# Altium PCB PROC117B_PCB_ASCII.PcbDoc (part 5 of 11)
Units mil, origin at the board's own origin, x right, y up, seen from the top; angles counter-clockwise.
Board outline 2480.32 x 3185.25 mil, 8 copper layers (Top Layer, L2_GND1, L3_SIG1, L4_PWR1, L5_PWR2, L6_SIG2, L7_GND2, Bottom Layer), stack 57.4 mil thick; 456 components, 292 nets, 7831 pads, 2905 vias.
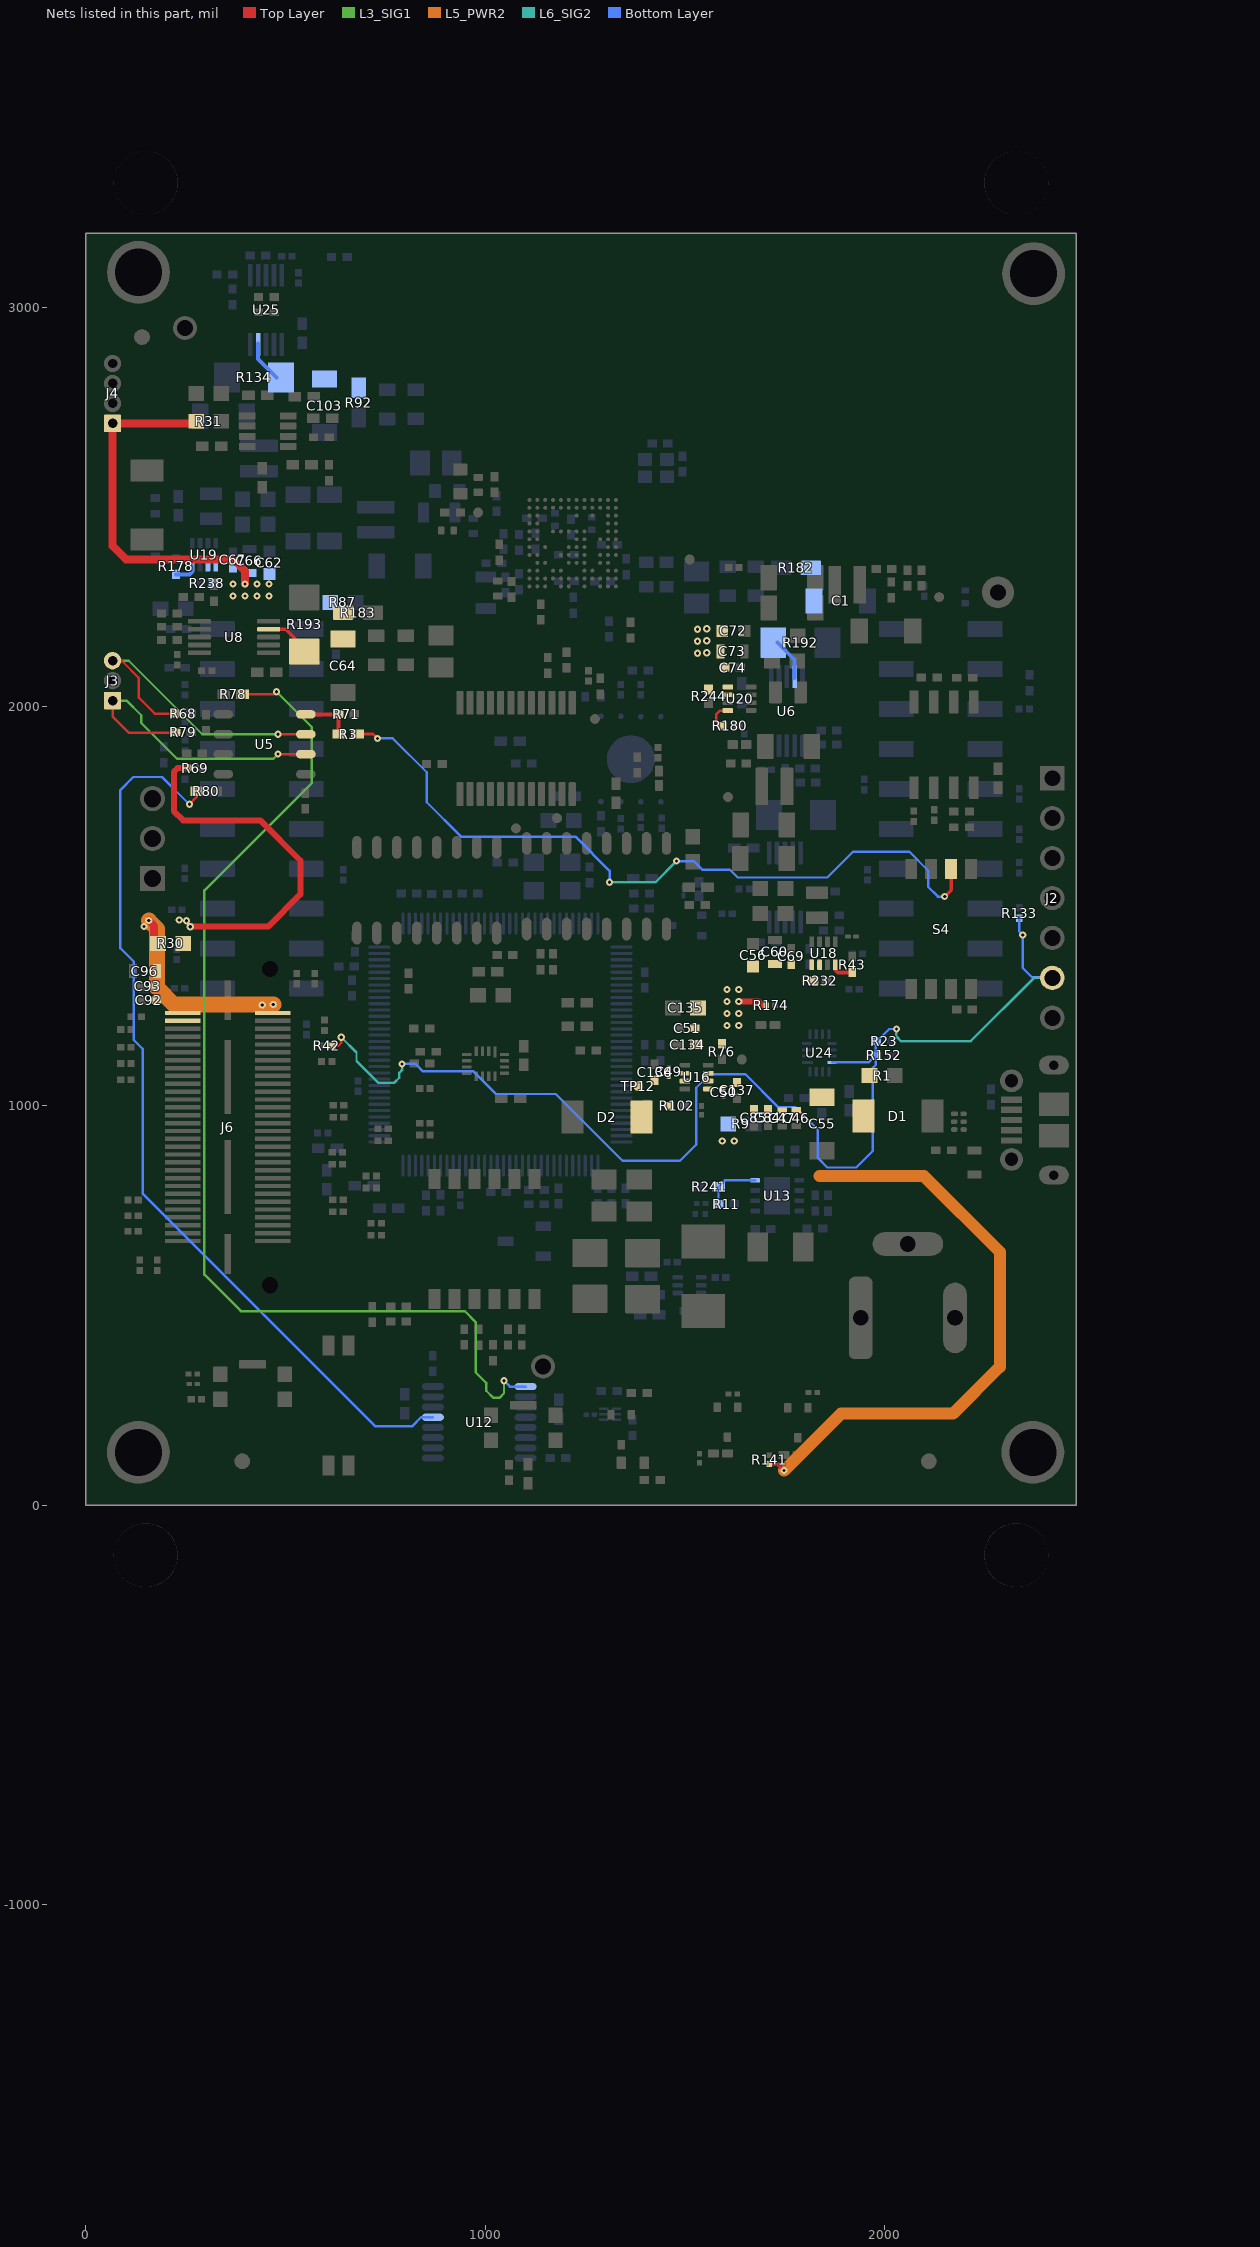
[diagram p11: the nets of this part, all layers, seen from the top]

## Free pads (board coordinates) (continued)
  round 5 on Mech26: 1(807.05,1390.43) 1(807.05,1390.43) 1(807.05,1441.43) 1(807.05,1441.43) 1(818.3,1366.43) 1(818.3,1366.43) 1(818.3,1374.58) 1(818.3,1374.58) 1(818.3,1376.86) 1(818.3,1376.86) 1(818.3,1384.36) 1(818.3,1384.36) 1(818.3,1390.43) 1(818.3,1390.43) 1(827.33,1093.94) 1(827.33,1093.94) 1(827.33,1093.96) 1(827.33,1093.96) 1(827.33,1150.96) 1(827.33,1150.96) 1(827.33,1150.98) 1(827.33,1150.98) 1(830.33,1090.96) 1(830.33,1090.96) 1(830.33,1153.96) 1(830.33,1153.96) 1(835.8,1366.43) 1(835.8,1366.43) 1(835.8,1374.58) 1(835.8,1374.58) 1(835.8,1376.86) 1(835.8,1376.86) 1(835.8,1384.36) 1(835.8,1384.36) 1(835.8,1390.43) 1(835.8,1390.43) 1(839.95,1066.46) 1(839.95,1066.46) 1(839.95,1075.01) 1(839.95,1075.01) 1(839.95,1078.65) 1(839.95,1078.65) 1(839.95,1079.91) 1(839.95,1079.91) 1(839.95,1089.87) 1(839.95,1089.87) 1(839.95,1090.96) 1(839.95,1090.96) 1(839.95,1153.96) 1(839.95,1153.96) 1(839.95,1155.04) 1(839.95,1155.04) 1(839.95,1165.01) 1(839.95,1165.01) 1(839.95,1166.27) 1(839.95,1166.27) 1(839.95,1169.91) 1(839.95,1169.91) 1(839.95,1178.46) 1(839.95,1178.46) 1(854.71,1066.46) 1(854.71,1066.46) 1(854.71,1075.01) 1(854.71,1075.01) 1(854.71,1078.65) 1(854.71,1078.65) 1(854.71,1079.91) 1(854.71,1079.91) 1(854.71,1089.87) 1(854.71,1089.87) 1(854.71,1090.96) 1(854.71,1090.96) 1(854.71,1153.96) 1(854.71,1153.96) 1(854.71,1155.04) 1(854.71,1155.04) 1(854.71,1165.01) 1(854.71,1165.01) 1(854.71,1166.27) 1(854.71,1166.27) 1(854.71,1169.91) 1(854.71,1169.91) 1(854.71,1178.46) 1(854.71,1178.46) 1(855.8,1441.43) 1(855.8,1441.43) 1(855.8,1447.49) 1(855.8,1447.49) 1(855.8,1454.99) 1(855.8,1454.99) 1(855.8,1457.27) 1(855.8,1457.27) 1(855.8,1465.43) 1(855.8,1465.43) 1(873.3,1441.43) 1(873.3,1441.43) 1(873.3,1447.49) 1(873.3,1447.49) 1(873.3,1454.99) 1(873.3,1454.99) 1(873.3,1457.27) 1(873.3,1457.27) 1(873.3,1465.43) 1(873.3,1465.43) 1(877.45,1066.46) 1(877.45,1066.46) 1(877.45,1075.01) 1(877.45,1075.01) 1(877.45,1078.65) 1(877.45,1078.65) 1(877.45,1079.91) 1(877.45,1079.91) 1(877.45,1089.87) 1(877.45,1089.87) 1(877.45,1090.96) 1(877.45,1090.96) 1(877.45,1153.96) 1(877.45,1153.96) 1(877.45,1155.04) 1(877.45,1155.04) 1(877.45,1165.01) 1(877.45,1165.01) 1(877.45,1166.27) 1(877.45,1166.27) 1(877.45,1169.91) 1(877.45,1169.91) 1(877.45,1178.46) 1(877.45,1178.46) 1(892.21,1066.46) 1(892.21,1066.46) 1(892.21,1075.01) 1(892.21,1075.01) 1(892.21,1078.65) 1(892.21,1078.65) 1(892.21,1079.91) 1(892.21,1079.91) 1(892.21,1089.87) 1(892.21,1089.87) 1(892.21,1090.96) 1(892.21,1090.96) 1(892.21,1153.96) 1(892.21,1153.96) 1(892.21,1155.04) 1(892.21,1155.04) 1(892.21,1165.01) 1(892.21,1165.01) 1(892.21,1166.27) 1(892.21,1166.27) 1(892.21,1169.91) 1(892.21,1169.91) 1(892.21,1178.46) 1(892.21,1178.46) 1(893.3,1366.43) 1(893.3,1366.43) 1(893.3,1374.58) 1(893.3,1374.58) 1(893.3,1376.86) 1(893.3,1376.86) 1(893.3,1384.36) 1(893.3,1384.36) 1(893.3,1390.43) 1(893.3,1390.43) 1(910.8,1366.43) 1(910.8,1366.43) 1(910.8,1374.58) 1(910.8,1374.58) 1(910.8,1376.86) 1(910.8,1376.86) 1(910.8,1384.36) 1(910.8,1384.36) 1(910.8,1390.43) 1(910.8,1390.43) 1(914.95,1066.46) 1(914.95,1066.46) 1(914.95,1075.01) 1(914.95,1075.01) 1(914.95,1078.65) 1(914.95,1078.65) 1(914.95,1079.91) 1(914.95,1079.91) 1(914.95,1089.87) 1(914.95,1089.87) 1(914.95,1090.96) 1(914.95,1090.96) 1(914.95,1153.96) 1(914.95,1153.96) 1(914.95,1155.04) 1(914.95,1155.04) 1(914.95,1165.01) 1(914.95,1165.01) 1(914.95,1166.27) 1(914.95,1166.27) 1(914.95,1169.91) 1(914.95,1169.91) 1(914.95,1178.46) 1(914.95,1178.46) 1(921.07,1099.78) 1(921.07,1099.78) 1(921.07,1109.78) 1(921.07,1109.78) 1(922.05,1390.43) 1(922.05,1390.43) 1(922.05,1441.43) 1(922.05,1441.43) 1(929.71,1066.46) 1(929.71,1066.46) 1(929.71,1075.01) 1(929.71,1075.01) 1(929.71,1078.65) 1(929.71,1078.65) 1(929.71,1079.91) 1(929.71,1079.91) 1(929.71,1089.87) 1(929.71,1089.87) 1(929.71,1090.96) 1(929.71,1090.96) 1(929.71,1153.96) 1(929.71,1153.96) 1(929.71,1155.04) 1(929.71,1155.04) 1(929.71,1165.01) 1(929.71,1165.01) 1(929.71,1166.27) 1(929.71,1166.27) 1(929.71,1169.91) 1(929.71,1169.91) 1(929.71,1178.46) 1(929.71,1178.46) 1(939.34,1090.96) 1(939.34,1090.96) 1(939.34,1153.96) 1(939.34,1153.96) 1(942.33,1093.94) 1(942.33,1093.94) 1(942.33,1093.96) 1(942.33,1093.96) 1(942.33,1150.96) 1(942.33,1150.96) 1(942.33,1150.98) 1(942.33,1150.98) 1(1048.4,-1695.57) 1(1048.4,-1695.57) 1(1048.4,-1195.57) 1(1048.4,-1195.57) 1(1638.7,1030.73) 1(1638.7,1030.73) 1(1638.7,1040.58) 1(1638.7,1040.58) 1(1638.7,1056.32) 1(1638.7,1056.32) 1(1638.7,1066.17) 1(1638.7,1066.17) 1(1638.7,1081.91) 1(1638.7,1081.91) 1(1638.7,1091.76) 1(1638.7,1091.76) 1(1638.7,1107.5) 1(1638.7,1107.5) 1(1638.7,1117.35) 1(1638.7,1117.35) 1(1650.51,1030.73) 1(1650.51,1030.73) 1(1650.51,1040.58) 1(1650.51,1040.58) 1(1650.51,1056.32) 1(1650.51,1056.32) 1(1650.51,1066.17) 1(1650.51,1066.17) 1(1650.51,1081.91) 1(1650.51,1081.91) 1(1650.51,1091.76) 1(1650.51,1091.76) 1(1650.51,1107.5) 1(1650.51,1107.5) 1(1650.51,1117.35) 1(1650.51,1117.35) 1(1655.94,1030.73) 1(1655.94,1030.73) 1(1655.94,1040.58) 1(1655.94,1040.58) 1(1655.94,1056.32) 1(1655.94,1056.32) 1(1655.94,1066.17) 1(1655.94,1066.17) 1(1655.94,1081.91) 1(1655.94,1081.91) 1(1655.94,1091.76) 1(1655.94,1091.76) 1(1655.94,1107.5) 1(1655.94,1107.5) 1(1655.94,1117.35) 1(1655.94,1117.35) 1(1661.16,1030.73) 1(1661.16,1030.73) 1(1661.16,1040.58) 1(1661.16,1040.58) 1(1661.16,1056.32) 1(1661.16,1056.32) 1(1661.16,1066.17) 1(1661.16,1066.17) 1(1661.16,1081.91) 1(1661.16,1081.91) 1(1661.16,1091.76) 1(1661.16,1091.76) 1(1661.16,1107.5) 1(1661.16,1107.5) 1(1661.16,1117.35) 1(1661.16,1117.35) 1(1670.2,1030.73) 1(1670.2,1030.73) 1(1670.2,1040.58) 1(1670.2,1040.58) 1(1670.2,1056.32) 1(1670.2,1056.32) 1(1670.2,1066.17) 1(1670.2,1066.17) 1(1670.2,1081.91) 1(1670.2,1081.91) 1(1670.2,1091.76) 1(1670.2,1091.76) 1(1670.2,1107.5) 1(1670.2,1107.5) 1(1670.2,1117.35) 1(1670.2,1117.35) 1(1676.11,1012.82) 1(1676.11,1012.82) 1(1676.11,1012.82) 1(1676.11,1030.73) 1(1676.11,1030.73) 1(1676.11,1040.58) 1(1676.11,1040.58) 1(1676.11,1056.32) 1(1676.11,1056.32) 1(1676.11,1066.17) 1(1676.11,1066.17) 1(1676.11,1081.91) 1(1676.11,1081.91) 1(1676.11,1091.76) 1(1676.11,1091.76) 1(1676.11,1107.5) 1(1676.11,1107.5) 1(1676.11,1117.35) 1(1676.11,1117.35) 1(1676.11,1134.87) 1(1676.11,1134.87) 1(1676.11,1134.87) 1(1679.87,1016.59) 1(1679.87,1016.59) 1(1679.87,1016.59) 1(1679.87,1131.1) 1(1679.87,1131.1) 1(1679.87,1131.1) 1(1694.66,881.81) 1(1694.66,881.81) 1(1694.66,892.49) 1(1694.66,892.49) 1(1694.66,901.49) 1(1694.66,901.49) 1(1694.66,912.17) 1(1694.66,912.17) 1(1694.66,940.85) 1(1694.66,940.85) 1(1694.66,951.53) 1(1694.66,951.53) 1(1694.66,872.81) 1(1694.66,872.81) 1(1694.66,921.17) 1(1694.66,921.17) 1(1694.66,931.85) 1(1694.66,931.85) 1(1694.66,960.53) 1(1694.66,960.53) 1(1695.79,1024.63) 1(1695.79,1024.63) 1(1695.79,1040.38) 1(1695.79,1040.38) 1(1704.1,872.81) 1(1704.1,872.81) 1(1704.1,881.81) 1(1704.1,881.81) 1(1704.1,892.49) 1(1704.1,892.49) 1(1704.1,901.49) 1(1704.1,901.49) 1(1704.1,912.17) 1(1704.1,912.17) 1(1704.1,921.17) 1(1704.1,921.17) 1(1704.1,931.85) 1(1704.1,931.85) 1(1704.1,940.85) 1(1704.1,940.85) 1(1704.1,951.53) 1(1704.1,951.53) 1(1704.1,960.53) 1(1704.1,960.53) 1(1708.82,872.81) 1(1708.82,872.81) 1(1708.82,881.81) 1(1708.82,881.81) 1(1708.82,892.49) 1(1708.82,892.49) 1(1708.82,901.49) 1(1708.82,901.49) 1(1708.82,912.17) 1(1708.82,912.17) 1(1708.82,921.17) 1(1708.82,921.17) 1(1708.82,931.85) 1(1708.82,931.85) 1(1708.82,940.85) 1(1708.82,940.85) 1(1708.82,951.53) 1(1708.82,951.53) 1(1708.82,960.53) 1(1708.82,960.53) 1(1708.95,872.81) 1(1708.95,872.81) 1(1708.95,881.81) 1(1708.95,881.81) 1(1708.95,892.49) 1(1708.95,892.49) 1(1708.95,901.49) 1(1708.95,901.49) 1(1708.95,912.17) 1(1708.95,912.17) 1(1708.95,921.17) 1(1708.95,921.17) 1(1708.95,931.85) 1(1708.95,931.85) 1(1708.95,940.85) 1(1708.95,940.85) 1(1708.95,951.53) 1(1708.95,951.53) 1(1708.95,960.53) 1(1708.95,960.53) 1(1720.9,872.81) 1(1720.9,872.81) 1(1720.9,881.81) 1(1720.9,881.81) 1(1720.9,892.49) 1(1720.9,892.49) 1(1720.9,901.49) 1(1720.9,901.49) 1(1720.9,912.17) 1(1720.9,912.17) 1(1720.9,921.17) 1(1720.9,921.17) 1(1720.9,931.85) 1(1720.9,931.85) 1(1720.9,940.85) 1(1720.9,940.85) 1(1720.9,951.53) 1(1720.9,951.53) 1(1720.9,960.53) 1(1720.9,960.53) 1(1732.16,862.67) 1(1732.16,862.67) 1(1732.16,872.81) 1(1732.16,872.81) 1(1732.16,881.81) 1(1732.16,881.81) 1(1732.16,892.49) 1(1732.16,892.49) 1(1732.16,901.49) 1(1732.16,901.49) 1(1732.16,912.17) 1(1732.16,912.17) 1(1732.16,921.17) 1(1732.16,921.17) 1(1732.16,931.85) 1(1732.16,931.85) 1(1732.16,940.85) 1(1732.16,940.85) 1(1732.16,951.53) 1(1732.16,951.53) 1(1732.16,960.53) 1(1732.16,960.53) 1(1732.16,970.67) 1(1732.16,970.67) 1(1732.16,862.57) 1(1732.16,862.57) 1(1732.16,970.78) 1(1732.16,970.78) 1(1733.24,95.75) 1(1733.24,95.75) 1(1733.24,175.75) 1(1733.24,175.75) 1(1733.24,491.89) 1(1733.24,491.89) 1(1733.24,571.89) 1(1733.24,571.89) 1(1737.05,857.67) 1(1737.05,857.67) 1(1737.05,975.67) 1(1737.05,975.67) 1(1737.16,857.67) 1(1737.16,857.67) 1(1737.16,975.67) 1(1737.16,975.67) 1(1739.16,878.67) 1(1739.16,878.67) 1(1752.97,-254.41) 1(1752.97,-254.41) 1(1752.97,-243.73) 1(1752.97,-243.73) 1(1752.97,-234.73) 1(1752.97,-234.73) 1(1752.97,-224.05) 1(1752.97,-224.05) 1(1752.97,-195.37) 1(1752.97,-195.37) 1(1752.97,-184.69) 1(1752.97,-184.69) 1(1752.97,-263.41) 1(1752.97,-263.41) 1(1752.97,-215.05) 1(1752.97,-215.05) 1(1752.97,-204.37) 1(1752.97,-204.37) 1(1752.97,-175.69) 1(1752.97,-175.69) 1(1762.4,-263.41) 1(1762.4,-263.41) 1(1762.4,-254.41) 1(1762.4,-254.41) 1(1762.4,-243.73) 1(1762.4,-243.73) 1(1762.4,-234.73) 1(1762.4,-234.73) 1(1762.4,-224.05) 1(1762.4,-224.05) 1(1762.4,-215.05) 1(1762.4,-215.05) 1(1762.4,-204.37) 1(1762.4,-204.37) 1(1762.4,-195.37) 1(1762.4,-195.37) 1(1762.4,-184.69) 1(1762.4,-184.69) 1(1762.4,-175.69) 1(1762.4,-175.69) 1(1767.12,-263.41) 1(1767.12,-263.41) 1(1767.12,-254.41) 1(1767.12,-254.41) 1(1767.12,-243.73) 1(1767.12,-243.73) 1(1767.12,-234.73) 1(1767.12,-234.73) 1(1767.12,-224.05) 1(1767.12,-224.05) 1(1767.12,-215.05) 1(1767.12,-215.05) 1(1767.12,-204.37) 1(1767.12,-204.37) 1(1767.12,-195.37) 1(1767.12,-195.37) 1(1767.12,-184.69) 1(1767.12,-184.69) 1(1767.12,-175.69) 1(1767.12,-175.69) 1(1767.16,878.67) 1(1767.16,878.67) 1(1767.25,-263.41) 1(1767.25,-263.41) 1(1767.25,-254.41) 1(1767.25,-254.41) 1(1767.25,-243.73) 1(1767.25,-243.73) 1(1767.25,-234.73) 1(1767.25,-234.73) 1(1767.25,-224.05) 1(1767.25,-224.05) 1(1767.25,-215.05) 1(1767.25,-215.05) 1(1767.25,-204.37) 1(1767.25,-204.37) 1(1767.25,-195.37) 1(1767.25,-195.37) 1(1767.25,-184.69) 1(1767.25,-184.69) 1(1767.25,-175.69) 1(1767.25,-175.69) 1(1779.21,-263.41) 1(1779.21,-263.41) 1(1779.21,-254.41) 1(1779.21,-254.41) 1(1779.21,-243.73) 1(1779.21,-243.73) 1(1779.21,-234.73) 1(1779.21,-234.73) 1(1779.21,-224.05) 1(1779.21,-224.05) 1(1779.21,-215.05) 1(1779.21,-215.05) 1(1779.21,-204.37) 1(1779.21,-204.37) 1(1779.21,-195.37) 1(1779.21,-195.37) 1(1779.21,-184.69) 1(1779.21,-184.69) 1(1779.21,-175.69) 1(1779.21,-175.69) 1(1790.47,-273.55) 1(1790.47,-273.55) 1(1790.47,-263.41) 1(1790.47,-263.41) 1(1790.47,-254.41) 1(1790.47,-254.41) 1(1790.47,-243.73) 1(1790.47,-243.73) 1(1790.47,-234.73) 1(1790.47,-234.73) 1(1790.47,-224.05) 1(1790.47,-224.05) 1(1790.47,-215.05) 1(1790.47,-215.05) 1(1790.47,-204.37) 1(1790.47,-204.37) 1(1790.47,-195.37) 1(1790.47,-195.37) 1(1790.47,-184.69) 1(1790.47,-184.69) 1(1790.47,-175.69) 1(1790.47,-175.69) 1(1790.47,-165.55) 1(1790.47,-165.55) 1(1790.47,-273.66) 1(1790.47,-273.66) 1(1790.47,-165.44) 1(1790.47,-165.44) 1(1795.36,-278.55) 1(1795.36,-278.55) 1(1795.36,-160.55) 1(1795.36,-160.55) 1(1795.47,-278.55) 1(1795.47,-278.55) 1(1795.47,-160.55) 1(1795.47,-160.55) 1(1797.47,-257.55) 1(1797.47,-257.55) 1(1825.47,-257.55) 1(1825.47,-257.55) 1(1845.16,857.67) 1(1845.16,857.67) 1(1845.16,975.67) 1(1845.16,975.67) 1(1845.27,857.67) 1(1845.27,857.67) 1(1845.27,975.67) 1(1845.27,975.67) 1(1849.5,1016.59) 1(1849.5,1016.59) 1(1849.5,1016.59) 1(1849.5,1131.1) 1(1849.5,1131.1) 1(1849.5,1131.1) 1(1850.16,862.57) 1(1850.16,862.57) 1(1850.16,970.78) 1(1850.16,970.78) 1(1850.16,862.67) 1(1850.16,862.67) 1(1850.16,872.81) 1(1850.16,872.81) 1(1850.16,881.81) 1(1850.16,881.81) 1(1850.16,892.49) 1(1850.16,892.49) 1(1850.16,901.49) 1(1850.16,901.49) 1(1850.16,912.17) 1(1850.16,912.17) 1(1850.16,921.17) 1(1850.16,921.17) 1(1850.16,931.85) 1(1850.16,931.85) 1(1850.16,940.85) 1(1850.16,940.85) 1(1850.16,951.53) 1(1850.16,951.53) 1(1850.16,960.53) 1(1850.16,960.53) 1(1850.16,970.67) 1(1850.16,970.67) 1(1853.27,1012.82) 1(1853.27,1012.82) 1(1853.27,1012.82) 1(1853.27,1030.73) 1(1853.27,1030.73) 1(1853.27,1040.58) 1(1853.27,1040.58) 1(1853.27,1056.32) 1(1853.27,1056.32) 1(1853.27,1066.17) 1(1853.27,1066.17) 1(1853.27,1081.91) 1(1853.27,1081.91) 1(1853.27,1091.76) 1(1853.27,1091.76) 1(1853.27,1107.5) 1(1853.27,1107.5) 1(1853.27,1117.35) 1(1853.27,1117.35) 1(1853.27,1134.87) 1(1853.27,1134.87) 1(1853.27,1134.87) 1(1859.18,1030.73) 1(1859.18,1030.73) 1(1859.18,1040.58) 1(1859.18,1040.58) 1(1859.18,1056.32) 1(1859.18,1056.32) 1(1859.18,1066.17) 1(1859.18,1066.17) 1(1859.18,1081.91) 1(1859.18,1081.91) 1(1859.18,1091.76) 1(1859.18,1091.76) 1(1859.18,1107.5) 1(1859.18,1107.5) 1(1859.18,1117.35) 1(1859.18,1117.35) 1(1861.43,872.81) 1(1861.43,872.81) 1(1861.43,881.81) 1(1861.43,881.81) 1(1861.43,892.49) 1(1861.43,892.49) 1(1861.43,901.49) 1(1861.43,901.49) 1(1861.43,912.17) 1(1861.43,912.17) 1(1861.43,921.17) 1(1861.43,921.17) 1(1861.43,931.85) 1(1861.43,931.85) 1(1861.43,960.53) 1(1861.43,960.53) 1(1861.43,940.85) 1(1861.43,940.85) 1(1861.43,951.53) 1(1861.43,951.53) 1(1868.22,1030.73) 1(1868.22,1030.73) 1(1868.22,1040.58) 1(1868.22,1040.58) 1(1868.22,1056.32) 1(1868.22,1056.32) 1(1868.22,1066.17) 1(1868.22,1066.17) 1(1868.22,1081.91) 1(1868.22,1081.91) 1(1868.22,1091.76) 1(1868.22,1091.76) 1(1868.22,1107.5) 1(1868.22,1107.5) 1(1868.22,1117.35) 1(1868.22,1117.35) 1(1873.38,872.81) 1(1873.38,872.81) 1(1873.38,881.81) 1(1873.38,881.81) 1(1873.38,892.49) 1(1873.38,892.49) 1(1873.38,901.49) 1(1873.38,901.49) 1(1873.38,912.17) 1(1873.38,912.17) 1(1873.38,921.17) 1(1873.38,921.17) 1(1873.38,931.85) 1(1873.38,931.85) 1(1873.38,940.85) 1(1873.38,940.85) 1(1873.38,951.53) 1(1873.38,951.53) 1(1873.38,960.53) 1(1873.38,960.53) 1(1873.44,1030.73) 1(1873.44,1030.73) 1(1873.44,1040.58) 1(1873.44,1040.58) 1(1873.44,1056.32) 1(1873.44,1056.32) 1(1873.44,1066.17) 1(1873.44,1066.17) 1(1873.44,1081.91) 1(1873.44,1081.91) 1(1873.44,1091.76) 1(1873.44,1091.76) 1(1873.44,1107.5) 1(1873.44,1107.5) 1(1873.44,1117.35) 1(1873.44,1117.35) 1(1873.51,940.85) 1(1873.51,940.85) 1(1873.51,951.53) 1(1873.51,951.53) 1(1873.51,872.81) 1(1873.51,872.81) 1(1873.51,881.81) 1(1873.51,881.81) 1(1873.51,892.49) 1(1873.51,892.49) 1(1873.51,901.49) 1(1873.51,901.49) 1(1873.51,912.17) 1(1873.51,912.17) 1(1873.51,921.17) 1(1873.51,921.17) 1(1873.51,931.85) 1(1873.51,931.85) 1(1873.51,960.53) 1(1873.51,960.53) 1(1878.23,872.81) 1(1878.23,872.81) 1(1878.23,881.81) 1(1878.23,881.81) 1(1878.23,892.49) 1(1878.23,892.49) 1(1878.23,901.49) 1(1878.23,901.49) 1(1878.23,912.17) 1(1878.23,912.17) 1(1878.23,921.17) 1(1878.23,921.17) 1(1878.23,931.85) 1(1878.23,931.85) 1(1878.23,940.85) 1(1878.23,940.85) 1(1878.23,951.53) 1(1878.23,951.53) 1(1878.23,960.53) 1(1878.23,960.53) 1(1878.86,1030.73) 1(1878.86,1030.73) 1(1878.86,1040.58) 1(1878.86,1040.58) 1(1878.86,1056.32) 1(1878.86,1056.32) 1(1878.86,1066.17) 1(1878.86,1066.17) 1(1878.86,1081.91) 1(1878.86,1081.91) 1(1878.86,1091.76) 1(1878.86,1091.76) 1(1878.86,1107.5) 1(1878.86,1107.5) 1(1878.86,1117.35) 1(1878.86,1117.35) 1(1879.24,491.89) 1(1879.24,491.89) 1(1879.24,571.89) 1(1879.24,571.89) 1(1881.24,95.75) 1(1881.24,95.75) 1(1881.24,95.89) 1(1881.24,95.89) 1(1881.24,175.75) 1(1881.24,175.75) 1(1881.24,175.89) 1(1881.24,175.89) 1(1881.24,491.89) 1(1881.24,491.89) 1(1881.24,571.89) 1(1881.24,571.89) 1(1887.66,872.81) 1(1887.66,872.81) 1(1887.66,881.81) 1(1887.66,881.81) 1(1887.66,892.49) 1(1887.66,892.49) 1(1887.66,901.49) 1(1887.66,901.49) 1(1887.66,912.17) 1(1887.66,912.17) 1(1887.66,921.17) 1(1887.66,921.17) 1(1887.66,931.85) 1(1887.66,931.85) 1(1887.66,940.85) 1(1887.66,940.85) 1(1887.66,951.53) 1(1887.66,951.53) 1(1887.66,960.53) 1(1887.66,960.53) 1(1890.67,1030.73) 1(1890.67,1030.73) 1(1890.67,1040.58) 1(1890.67,1040.58) 1(1890.67,1056.32) 1(1890.67,1056.32) 1(1890.67,1066.17) 1(1890.67,1066.17) 1(1890.67,1081.91) 1(1890.67,1081.91) 1(1890.67,1091.76) 1(1890.67,1091.76) 1(1890.67,1107.5) 1(1890.67,1107.5) 1(1890.67,1117.35) 1(1890.67,1117.35) 1(1903.47,-278.55) 1(1903.47,-278.55) 1(1903.47,-160.55) 1(1903.47,-160.55) 1(1903.58,-278.55) 1(1903.58,-278.55) 1(1903.58,-160.55) 1(1903.58,-160.55) 1(1908.47,-273.66) 1(1908.47,-273.66) 1(1908.47,-165.44) 1(1908.47,-165.44) 1(1908.47,-273.55) 1(1908.47,-273.55) 1(1908.47,-263.41) 1(1908.47,-263.41) 1(1908.47,-254.41) 1(1908.47,-254.41) 1(1908.47,-243.73) 1(1908.47,-243.73) 1(1908.47,-234.73) 1(1908.47,-234.73) 1(1908.47,-224.05) 1(1908.47,-224.05) 1(1908.47,-215.05) 1(1908.47,-215.05) 1(1908.47,-204.37) 1(1908.47,-204.37) 1(1908.47,-195.37) 1(1908.47,-195.37) 1(1908.47,-184.69) 1(1908.47,-184.69) 1(1908.47,-175.69) 1(1908.47,-175.69) 1(1908.47,-165.55) 1(1908.47,-165.55) 1(1919.73,-263.41) 1(1919.73,-263.41) 1(1919.73,-254.41) 1(1919.73,-254.41) 1(1919.73,-243.73) 1(1919.73,-243.73) 1(1919.73,-234.73) 1(1919.73,-234.73) 1(1919.73,-224.05) 1(1919.73,-224.05) 1(1919.73,-215.05) 1(1919.73,-215.05) 1(1919.73,-204.37) 1(1919.73,-204.37) 1(1919.73,-175.69) 1(1919.73,-175.69) 1(1919.73,-195.37) 1(1919.73,-195.37) 1(1919.73,-184.69) 1(1919.73,-184.69) 1(1931.69,-263.41) 1(1931.69,-263.41) 1(1931.69,-254.41) 1(1931.69,-254.41) 1(1931.69,-243.73) 1(1931.69,-243.73) 1(1931.69,-234.73) 1(1931.69,-234.73) 1(1931.69,-224.05) 1(1931.69,-224.05) 1(1931.69,-215.05) 1(1931.69,-215.05) 1(1931.69,-204.37) 1(1931.69,-204.37) 1(1931.69,-195.37) 1(1931.69,-195.37) 1(1931.69,-184.69) 1(1931.69,-184.69) 1(1931.69,-175.69) 1(1931.69,-175.69) 1(1931.82,-195.37) 1(1931.82,-195.37) 1(1931.82,-184.69) 1(1931.82,-184.69) 1(1931.82,-263.41) 1(1931.82,-263.41) 1(1931.82,-254.41) 1(1931.82,-254.41) 1(1931.82,-243.73) 1(1931.82,-243.73) 1(1931.82,-234.73) 1(1931.82,-234.73) 1(1931.82,-224.05) 1(1931.82,-224.05) 1(1931.82,-215.05) 1(1931.82,-215.05) 1(1931.82,-204.37) 1(1931.82,-204.37) 1(1931.82,-175.69) 1(1931.82,-175.69) 1(1936.53,-263.41) 1(1936.53,-263.41) 1(1936.53,-254.41) 1(1936.53,-254.41) 1(1936.53,-243.73) 1(1936.53,-243.73) 1(1936.53,-234.73) 1(1936.53,-234.73) 1(1936.53,-224.05) 1(1936.53,-224.05) 1(1936.53,-215.05) 1(1936.53,-215.05) 1(1936.53,-204.37) 1(1936.53,-204.37) 1(1936.53,-195.37) 1(1936.53,-195.37) 1(1936.53,-184.69) 1(1936.53,-184.69) 1(1936.53,-175.69) 1(1936.53,-175.69) 1(1945.97,-263.41) 1(1945.97,-263.41) 1(1945.97,-254.41) 1(1945.97,-254.41) 1(1945.97,-243.73) 1(1945.97,-243.73) 1(1945.97,-234.73) 1(1945.97,-234.73) 1(1945.97,-224.05) 1(1945.97,-224.05) 1(1945.97,-215.05) 1(1945.97,-215.05) 1(1945.97,-204.37) 1(1945.97,-204.37) 1(1945.97,-195.37) 1(1945.97,-195.37) 1(1945.97,-184.69) 1(1945.97,-184.69) 1(1945.97,-175.69) 1(1945.97,-175.69) 1(1948.4,-1695.57) 1(1948.4,-1695.57) 1(1948.4,-1195.57) 1(1948.4,-1195.57) 1(2027.24,491.89) 1(2027.24,491.89) 1(2027.24,571.89) 1(2027.24,571.89) 1(2029.24,95.89) 1(2029.24,95.89) 1(2029.24,175.89) 1(2029.24,175.89) 1(2063.02,-1665.07) 1(2063.02,-1665.07) 1(2063.02,-1656.08) 1(2063.02,-1656.08) 1(2063.02,-1517.07) 1(2063.02,-1517.07) 1(2063.02,-1508.07) 1(2063.02,-1508.07) 1(2212.85,-47.93) 1(2212.85,-47.93) 1(2212.85,-38.93) 1(2212.85,-38.93) 1(2212.85,-28.25) 1(2212.85,-28.25) 1(2212.85,-19.25) 1(2212.85,-19.25) 1(2212.85,-8.57) 1(2212.85,-8.57) 1(2212.85,0.43) 1(2212.85,0.43) 1(2212.85,11.11) 1(2212.85,11.11) 1(2212.85,20.11) 1(2212.85,20.11) 1(2212.85,30.79) 1(2212.85,30.79) 1(2212.85,39.79) 1(2212.85,39.79) 1(2222.29,-47.93) 1(2222.29,-47.93) 1(2222.29,-38.93) 1(2222.29,-38.93) 1(2222.29,-28.25) 1(2222.29,-28.25) 1(2222.29,-19.25) 1(2222.29,-19.25) 1(2222.29,-8.57) 1(2222.29,-8.57) 1(2222.29,0.43) 1(2222.29,0.43) 1(2222.29,11.11) 1(2222.29,11.11) 1(2222.29,20.11) 1(2222.29,20.11) 1(2222.29,30.79) 1(2222.29,30.79) 1(2222.29,39.79) 1(2222.29,39.79) 1(2227,-47.93) 1(2227,-47.93) 1(2227,-38.93) 1(2227,-38.93) 1(2227,-28.25) 1(2227,-28.25) 1(2227,-19.25) 1(2227,-19.25) 1(2227,-8.57) 1(2227,-8.57) 1(2227,0.43) 1(2227,0.43) 1(2227,11.11) 1(2227,11.11) 1(2227,20.11) 1(2227,20.11) 1(2227,30.79) 1(2227,30.79) 1(2227,39.79) 1(2227,39.79) 1(2227.13,-47.93) 1(2227.13,-47.93) 1(2227.13,-38.93) 1(2227.13,-38.93) 1(2227.13,-28.25) 1(2227.13,-28.25) 1(2227.13,-19.25) 1(2227.13,-19.25) 1(2227.13,-8.57) 1(2227.13,-8.57) 1(2227.13,0.43) 1(2227.13,0.43) 1(2227.13,11.11) 1(2227.13,11.11) 1(2227.13,20.11) 1(2227.13,20.11) 1(2227.13,30.79) 1(2227.13,30.79) 1(2227.13,39.79) 1(2227.13,39.79) 1(2239.09,-47.93) 1(2239.09,-47.93) 1(2239.09,-38.93) 1(2239.09,-38.93) 1(2239.09,-28.25) 1(2239.09,-28.25) 1(2239.09,-19.25) 1(2239.09,-19.25) 1(2239.09,-8.57) 1(2239.09,-8.57) 1(2239.09,0.43) 1(2239.09,0.43) 1(2239.09,11.11) 1(2239.09,11.11) 1(2239.09,20.11) 1(2239.09,20.11) 1(2239.09,30.79) 1(2239.09,30.79) 1(2239.09,39.79) 1(2239.09,39.79) 1(2250.35,-58.07) 1(2250.35,-58.07) 1(2250.35,-47.93) 1(2250.35,-47.93) 1(2250.35,-38.93) 1(2250.35,-38.93) 1(2250.35,-28.25) 1(2250.35,-28.25) 1(2250.35,-19.25) 1(2250.35,-19.25) 1(2250.35,-8.57) 1(2250.35,-8.57) 1(2250.35,0.43) 1(2250.35,0.43) 1(2250.35,11.11) 1(2250.35,11.11) 1(2250.35,20.11) 1(2250.35,20.11) 1(2250.35,30.79) 1(2250.35,30.79) 1(2250.35,39.79) 1(2250.35,39.79) 1(2250.35,49.93) 1(2250.35,49.93) 1(2250.35,-58.18) 1(2250.35,-58.18) 1(2250.35,50.04) 1(2250.35,50.04) 1(2251.39,-1440.52) 1(2251.39,-1440.52) 1(2251.39,-1292.52) 1(2251.39,-1292.52) 1(2255.24,-63.07) 1(2255.24,-63.07) 1(2255.24,54.93) 1(2255.24,54.93) 1(2255.35,-63.07) 1(2255.35,-63.07) 1(2255.35,54.93) 1(2255.35,54.93) 1(2330.02,-1665.07) 1(2330.02,-1508.07) 1(2331.39,-1440.52) 1(2331.39,-1440.52) 1(2331.39,-1292.52) 1(2331.39,-1292.52) 1(2333.35,33.93) 1(2333.35,33.93) 1(2341.39,-1440.52) 1(2341.39,-1440.52) 1(2341.39,-1292.52) 1(2341.39,-1292.52) 1(2361.35,33.93) 1(2361.35,33.93) 1(2363.35,-63.07) 1(2363.35,-63.07) 1(2363.35,54.93) 1(2363.35,54.93) 1(2363.46,-63.07) 1(2363.46,-63.07) 1(2363.46,54.93) 1(2363.46,54.93) 1(2368.35,-58.18) 1(2368.35,-58.18) 1(2368.35,50.04) 1(2368.35,50.04) 1(2368.35,-58.07) 1(2368.35,-58.07) 1(2368.35,-47.93) 1(2368.35,-47.93) 1(2368.35,-38.93) 1(2368.35,-38.93) 1(2368.35,-28.25) 1(2368.35,-28.25) 1(2368.35,-19.25) 1(2368.35,-19.25) 1(2368.35,-8.57) 1(2368.35,-8.57) 1(2368.35,0.43) 1(2368.35,0.43) 1(2368.35,11.11) 1(2368.35,11.11) 1(2368.35,20.11) 1(2368.35,20.11) 1(2368.35,30.79) 1(2368.35,30.79) 1(2368.35,39.79) 1(2368.35,39.79) 1(2368.35,49.93) 1(2368.35,49.93) 1(2379.61,-47.93) 1(2379.61,-47.93) 1(2379.61,-38.93) 1(2379.61,-38.93) 1(2379.61,-28.25) 1(2379.61,-28.25) 1(2379.61,-19.25) 1(2379.61,-19.25) 1(2379.61,-8.57) 1(2379.61,-8.57) 1(2379.61,0.43) 1(2379.61,0.43) 1(2379.61,11.11) 1(2379.61,11.11) 1(2379.61,20.11) 1(2379.61,20.11) 1(2379.61,30.79) 1(2379.61,30.79) 1(2379.61,39.79) 1(2379.61,39.79) 1(2391.57,-47.93) 1(2391.57,-47.93) 1(2391.57,-38.93) 1(2391.57,-38.93) 1(2391.57,-28.25) 1(2391.57,-28.25) 1(2391.57,-19.25) 1(2391.57,-19.25) 1(2391.57,-8.57) 1(2391.57,-8.57) 1(2391.57,0.43) 1(2391.57,0.43) 1(2391.57,11.11) 1(2391.57,11.11) 1(2391.57,20.11) 1(2391.57,20.11) 1(2391.57,30.79) 1(2391.57,30.79) 1(2391.57,39.79) 1(2391.57,39.79) 1(2391.7,-47.93) 1(2391.7,-47.93) 1(2391.7,-38.93) 1(2391.7,-38.93) 1(2391.7,-28.25) 1(2391.7,-28.25) 1(2391.7,-19.25) 1(2391.7,-19.25) 1(2391.7,-8.57) 1(2391.7,-8.57) 1(2391.7,0.43) 1(2391.7,0.43) 1(2391.7,11.11) 1(2391.7,11.11) 1(2391.7,20.11) 1(2391.7,20.11) 1(2391.7,30.79) 1(2391.7,30.79) 1(2391.7,39.79) 1(2391.7,39.79) 1(2396.42,-47.93) 1(2396.42,-47.93) 1(2396.42,-38.93) 1(2396.42,-38.93) 1(2396.42,-28.25) 1(2396.42,-28.25) 1(2396.42,-19.25) 1(2396.42,-19.25) 1(2396.42,-8.57) 1(2396.42,-8.57) 1(2396.42,0.43) 1(2396.42,0.43) 1(2396.42,11.11) 1(2396.42,11.11) 1(2396.42,20.11) 1(2396.42,20.11) 1(2396.42,30.79) 1(2396.42,30.79) 1(2396.42,39.79) 1(2396.42,39.79) 1(2405.85,-47.93) 1(2405.85,-47.93) 1(2405.85,-38.93) 1(2405.85,-38.93) 1(2405.85,-28.25) 1(2405.85,-28.25) 1(2405.85,-19.25) 1(2405.85,-19.25) 1(2405.85,-8.57) 1(2405.85,-8.57) 1(2405.85,0.43) 1(2405.85,0.43) 1(2405.85,11.11) 1(2405.85,11.11) 1(2405.85,20.11) 1(2405.85,20.11) 1(2405.85,30.79) 1(2405.85,30.79) 1(2405.85,39.79) 1(2405.85,39.79) 1(2421.39,-1440.52) 1(2421.39,-1440.52) 1(2421.39,-1292.52) 1(2421.39,-1292.52) 1(2491.39,2367.48) 1(2491.39,2367.48) 1(2491.39,2515.48) 1(2491.39,2515.48) 1(2571.39,2367.48) 1(2571.39,2367.48) 1(2571.39,2515.48) 1(2571.39,2515.48) 1(2608.3,1474.17) 1(2608.3,1474.17) 1(2608.3,1493.85) 1(2608.3,1493.85) 1(2608.3,1514.13) 1(2608.3,1514.13) 1(2608.3,1537.16) 1(2608.3,1537.16) 1(2608.3,1631.65) 1(2608.3,1631.65) 1(2608.3,1654.68) 1(2608.3,1654.68) 1(2608.3,1674.96) 1(2608.3,1674.96) 1(2608.3,1694.64) 1(2608.3,1694.64) 1(2608.3,2149.17) 1(2608.3,2149.17) 1(2608.3,2168.85) 1(2608.3,2168.85) 1(2608.3,2189.13) 1(2608.3,2189.13) 1(2608.3,2212.16) 1(2608.3,2212.16) 1(2608.3,2306.65) 1(2608.3,2306.65) 1(2608.3,2329.68) 1(2608.3,2329.68) 1(2608.3,2349.96) 1(2608.3,2349.96) 1(2608.3,2369.64) 1(2608.3,2369.64) 1(2620.11,1436.77) 1(2620.11,1436.77) 1(2620.11,1458.42) 1(2620.11,1458.42) 1(2620.11,1474.17) 1(2620.11,1474.17) 1(2620.11,1694.64) 1(2620.11,1694.64) 1(2620.11,1710.39) 1(2620.11,1710.39) 1(2620.11,1732.04) 1(2620.11,1732.04) 1(2620.11,2111.77) 1(2620.11,2111.77) 1(2620.11,2133.42) 1(2620.11,2133.42) 1(2620.11,2149.17) 1(2620.11,2149.17) 1(2620.11,2369.64) 1(2620.11,2369.64) 1(2620.11,2385.39) 1(2620.11,2385.39) 1(2620.11,2407.04) 1(2620.11,2407.04) 1(2805.15,1436.77) 1(2805.15,1436.77) 1(2805.15,1436.77) 1(2805.15,1448.58) 1(2805.15,1458.42) 1(2805.15,1458.42) 1(2805.15,1458.42) 1(2805.15,1710.39) 1(2805.15,1710.39) 1(2805.15,1710.39) 1(2805.15,1720.23) 1(2805.15,1732.04) 1(2805.15,1732.04) 1(2805.15,1732.04) 1(2805.15,2111.77) 1(2805.15,2111.77) 1(2805.15,2111.77) 1(2805.15,2123.58) 1(2805.15,2133.42) 1(2805.15,2133.42) 1(2805.15,2133.42) 1(2805.15,2385.39) 1(2805.15,2385.39) 1(2805.15,2385.39) 1(2805.15,2395.23) 1(2805.15,2407.04) 1(2805.15,2407.04) 1(2805.15,2407.04) 1(2805.28,1448.58) 1(2805.28,1720.23) 1(2805.28,2123.58) 1(2805.28,2395.23) 1(2805.28,1448.58) 1(2805.28,1720.23) 1(2805.28,2123.58) 1(2805.28,2395.23) 1(2807.94,1458.42) 1(2807.94,1458.42) 1(2807.94,1458.42) 1(2807.94,1710.39) 1(2807.94,1710.39) 1(2807.94,1710.39) 1(2807.94,2133.42) 1(2807.94,2133.42) 1(2807.94,2133.42) 1(2807.94,2385.39) 1(2807.94,2385.39) 1(2807.94,2385.39) 1(2808.09,1430.18) 1(2808.09,1430.18) 1(2808.09,1738.63) 1(2808.09,1738.63) 1(2808.09,2105.18) 1(2808.09,2105.18) 1(2808.09,2413.63) 1(2808.09,2413.63) 1(2808.18,1710.38) 1(2808.18,1710.38) 1(2808.18,2385.38) 1(2808.18,2385.38) 1(2808.29,1458.44) 1(2808.29,1458.44) 1(2808.29,2133.44) 1(2808.29,2133.44) 1(2808.43,1710.35) 1(2808.43,1710.35) 1(2808.43,2385.35) 1(2808.43,2385.35) 1(2808.53,1458.48) 1(2808.53,1458.48) 1(2808.53,2133.48) 1(2808.53,2133.48) 1(2808.67,1710.3) 1(2808.67,1710.3) 1(2808.67,2385.3) 1(2808.67,2385.3) 1(2808.77,1458.53) 1(2808.77,1458.53) 1(2808.77,2133.53) 1(2808.77,2133.53) 1(2808.91,1710.23) 1(2808.91,1710.23) 1(2808.91,2385.23) 1(2808.91,2385.23) 1(2809.01,1458.61) 1(2809.01,1458.61) 1(2809.01,2133.61) 1(2809.01,2133.61) 1(2809.15,1710.14) 1(2809.15,1710.14) 1(2809.15,2385.14) 1(2809.15,2385.14) 1(2809.25,1458.71) 1(2809.25,1458.71) 1(2809.25,2133.71) 1(2809.25,2133.71) 1(2809.39,1710.04) 1(2809.39,1710.04) 1(2809.39,2385.04) 1(2809.39,2385.04) 1(2809.49,1458.82) 1(2809.49,1458.82) 1(2809.49,2133.82) 1(2809.49,2133.82) 1(2809.62,1709.91) 1(2809.62,1709.91) 1(2809.62,2384.91) 1(2809.62,2384.91) 1(2809.72,1458.96) 1(2809.72,1458.96) 1(2809.72,2133.96) 1(2809.72,2133.96) 1(2809.85,1709.77) 1(2809.85,1709.77) 1(2809.85,2384.77) 1(2809.85,2384.77) 1(2809.94,1459.11) 1(2809.94,1459.11) 1(2809.94,2134.11) 1(2809.94,2134.11) 1(2810.07,1709.61) 1(2810.07,1709.61) 1(2810.07,2384.61) 1(2810.07,2384.61) 1(2810.17,1459.28) 1(2810.17,1459.28) 1(2810.17,2134.28) 1(2810.17,2134.28) 1(2810.29,1709.42) 1(2810.29,1709.42) 1(2810.29,2384.42) 1(2810.29,2384.42) 1(2810.38,1459.46) 1(2810.38,1459.46) 1(2810.38,2134.46) 1(2810.38,2134.46) 1(2810.51,1709.23) 1(2810.51,1709.23) 1(2810.51,2384.23) 1(2810.51,2384.23) 1(2810.59,1459.67) 1(2810.59,1459.67) 1(2810.59,2134.67) 1(2810.59,2134.67) 1(2810.71,1709.01) 1(2810.71,1709.01) 1(2810.71,2384.01) 1(2810.71,2384.01) 1(2810.8,1459.89) 1(2810.8,1459.89) 1(2810.8,2134.89) 1(2810.8,2134.89) 1(2810.91,1708.78) 1(2810.91,1708.78) 1(2810.91,2383.78) 1(2810.91,2383.78) 1(2810.99,1460.13) 1(2810.99,1460.13) 1(2810.99,2135.13) 1(2810.99,2135.13) 1(2811.1,1708.54) 1(2811.1,1708.54) 1(2811.1,2383.54) 1(2811.1,2383.54) 1(2811.18,1460.38) 1(2811.18,1460.38) 1(2811.18,2135.38) 1(2811.18,2135.38) 1(2811.29,1708.28) 1(2811.29,1708.28) 1(2811.29,2383.28) 1(2811.29,2383.28) 1(2811.29,1422.99) 1(2811.29,1422.99) 1(2811.29,1745.82) 1(2811.29,1745.82) 1(2811.29,2097.99) 1(2811.29,2097.99) 1(2811.29,2420.82) 1(2811.29,2420.82) 1(2811.36,1460.65) 1(2811.36,1460.65) 1(2811.36,2135.65) 1(2811.36,2135.65) 1(2811.46,1708) 1(2811.46,1708) 1(2811.46,2383) 1(2811.46,2383) 1(2811.53,1460.93) 1(2811.53,1460.93) 1(2811.53,2135.93) 1(2811.53,2135.93) 1(2811.63,1707.71) 1(2811.63,1707.71) 1(2811.63,2382.71) 1(2811.63,2382.71) 1(2811.7,1461.22) 1(2811.7,1461.22) 1(2811.7,2136.22) 1(2811.7,2136.22) 1(2811.79,1707.41) 1(2811.79,1707.41) 1(2811.79,2382.41) 1(2811.79,2382.41) 1(2811.85,1461.53) 1(2811.85,1461.53) 1(2811.85,2136.53) 1(2811.85,2136.53) 1(2811.93,1707.1) 1(2811.93,1707.1) 1(2811.93,2382.1) 1(2811.93,2382.1) 1(2811.99,1461.85) 1(2811.99,1461.85) 1(2811.99,2136.85) 1(2811.99,2136.85) 1(2812.07,1706.77) 1(2812.07,1706.77) 1(2812.07,2381.77) 1(2812.07,2381.77) 1(2812.13,1462.18) 1(2812.13,1462.18) 1(2812.13,2137.18) 1(2812.13,2137.18) 1(2812.2,1706.43) 1(2812.2,1706.43) 1(2812.2,2381.43) 1(2812.2,2381.43) 1(2812.25,1462.52) 1(2812.25,1462.52) 1(2812.25,2137.52) 1(2812.25,2137.52) 1(2812.32,1706.09) 1(2812.32,1706.09) 1(2812.32,2381.09) 1(2812.32,2381.09) 1(2812.36,1462.87) 1(2812.36,1462.87) 1(2812.36,2137.87) 1(2812.36,2137.87) 1(2812.42,1705.73) 1(2812.42,1705.73) 1(2812.42,2380.73) 1(2812.42,2380.73) 1(2812.46,1463.23) 1(2812.46,1463.23) 1(2812.46,2138.23) 1(2812.46,2138.23) 1(2812.52,1705.37) 1(2812.52,1705.37) 1(2812.52,2380.37) 1(2812.52,2380.37) 1(2812.55,1463.59) 1(2812.55,1463.59) 1(2812.55,2138.59) 1(2812.55,2138.59) 1(2812.6,1705) 1(2812.6,1705) 1(2812.6,2380) 1(2812.6,2380) 1(2812.63,1463.97) 1(2812.63,1463.97) 1(2812.63,2138.97) 1(2812.63,2138.97) 1(2812.67,1704.62) 1(2812.67,1704.62) 1(2812.67,2379.62) 1(2812.67,2379.62) 1(2812.7,1464.35) 1(2812.7,1464.35) 1(2812.7,2139.35) 1(2812.7,2139.35) 1(2812.73,1704.24) 1(2812.73,1704.24) 1(2812.73,2379.24) 1(2812.73,2379.24) 1(2812.75,1464.73) 1(2812.75,1464.73) 1(2812.75,2139.73) 1(2812.75,2139.73) 1(2812.78,1703.85) 1(2812.78,1703.85) 1(2812.78,2378.85) 1(2812.78,2378.85) 1(2812.79,1465.12) 1(2812.79,1465.12) 1(2812.79,2140.12) 1(2812.79,2140.12) 1(2812.81,1703.46) 1(2812.81,1703.46) 1(2812.81,2378.46) 1(2812.81,2378.46) 1(2812.83,1465.51) 1(2812.83,1465.51) 1(2812.83,2140.51) 1(2812.83,2140.51) 1(2812.84,1703.07) 1(2812.84,1703.07) 1(2812.84,2378.07) 1(2812.84,2378.07) 1(2812.84,1465.9) 1(2812.84,1465.9) 1(2812.84,2140.9) 1(2812.84,2140.9) 1(2812.85,1466.29) 1(2812.85,1466.29) 1(2812.85,1702.51) 1(2812.85,1702.51) 1(2812.85,2141.29) 1(2812.85,2141.29) 1(2812.85,2377.51) 1(2812.85,2377.51) 1(2815.89,1441.69) 1(2815.89,1727.12) 1(2815.89,2116.69) 1(2815.89,2402.12) 1(2815.89,1441.69) 1(2815.89,1727.12) 1(2815.89,2116.69) 1(2815.89,2402.12) 1(2817.17,1458.42) 1(2817.17,1458.42) 1(2817.17,1710.39) 1(2817.17,1710.39) 1(2817.17,2133.42) 1(2817.17,2133.42) 1(2817.17,2385.39) 1(2817.17,2385.39) 1(2817.42,1710.38) 1(2817.42,1710.38) 1(2817.42,2385.38) 1(2817.42,2385.38) 1(2817.52,1458.44) 1(2817.52,1458.44) 1(2817.52,2133.44) 1(2817.52,2133.44) 1(2817.66,1710.35) 1(2817.66,1710.35) 1(2817.66,2385.35) 1(2817.66,2385.35) 1(2817.76,1458.48) 1(2817.76,1458.48) 1(2817.76,2133.48) 1(2817.76,2133.48) 1(2817.9,1710.3) 1(2817.9,1710.3) 1(2817.9,2385.3) 1(2817.9,2385.3) 1(2818.01,1458.53) 1(2818.01,1458.53) 1(2818.01,2133.53) 1(2818.01,2133.53) 1(2818.15,1710.23) 1(2818.15,1710.23) 1(2818.15,2385.23) 1(2818.15,2385.23) 1(2818.25,1458.61) 1(2818.25,1458.61) 1(2818.25,2133.61) 1(2818.25,2133.61) 1(2818.39,1710.14) 1(2818.39,1710.14) 1(2818.39,2385.14) 1(2818.39,2385.14) 1(2818.48,1458.71) 1(2818.48,1458.71) 1(2818.48,2133.71) 1(2818.48,2133.71) 1(2818.62,1710.04) 1(2818.62,1710.04) 1(2818.62,2385.04) 1(2818.62,2385.04) 1(2818.72,1458.82) 1(2818.72,1458.82) 1(2818.72,2133.82) 1(2818.72,2133.82) 1(2818.85,1709.91) 1(2818.85,1709.91) 1(2818.85,2384.91) 1(2818.85,2384.91) 1(2818.88,1434.99) 1(2818.88,1434.99) 1(2818.88,1733.82) 1(2818.88,1733.82) 1(2818.88,2109.99) 1(2818.88,2109.99) 1(2818.88,2408.82) 1(2818.88,2408.82) 1(2818.95,1458.96) 1(2818.95,1458.96) 1(2818.95,2133.96) 1(2818.95,2133.96) 1(2819.08,1709.77) 1(2819.08,1709.77) 1(2819.08,2384.77) 1(2819.08,2384.77) 1(2819.18,1459.11) 1(2819.18,1459.11) 1(2819.18,2134.11) 1(2819.18,2134.11) 1(2819.31,1709.61) 1(2819.31,1709.61) 1(2819.31,2384.61) 1(2819.31,2384.61) 1(2819.4,1459.28) 1(2819.4,1459.28) 1(2819.4,2134.28) 1(2819.4,2134.28) 1(2819.53,1709.42) 1(2819.53,1709.42) 1(2819.53,2384.42) 1(2819.53,2384.42) 1(2819.61,1459.46) 1(2819.61,1459.46) 1(2819.61,2134.46) 1(2819.61,2134.46) 1(2819.74,1709.23) 1(2819.74,1709.23) 1(2819.74,2384.23) 1(2819.74,2384.23) 1(2819.82,1459.67) 1(2819.82,1459.67) 1(2819.82,2134.67) 1(2819.82,2134.67) 1(2819.94,1709.01) 1(2819.94,1709.01) 1(2819.94,2384.01) 1(2819.94,2384.01) 1(2820.03,1459.89) 1(2820.03,1459.89) 1(2820.03,2134.89) 1(2820.03,2134.89) 1(2820.14,1708.78) 1(2820.14,1708.78) 1(2820.14,2383.78) 1(2820.14,2383.78) 1(2820.22,1460.13) 1(2820.22,1460.13) 1(2820.22,2135.13) 1(2820.22,2135.13) 1(2820.33,1708.54) 1(2820.33,1708.54) 1(2820.33,2383.54) 1(2820.33,2383.54) 1(2820.41,1460.38) 1(2820.41,1460.38) 1(2820.41,2135.38) 1(2820.41,2135.38) 1(2820.52,1708.28) 1(2820.52,1708.28) 1(2820.52,2383.28) 1(2820.52,2383.28) 1(2820.59,1460.65) 1(2820.59,1460.65) 1(2820.59,2135.65) 1(2820.59,2135.65) 1(2820.69,1708) 1(2820.69,1708) 1(2820.69,2383) 1(2820.69,2383) 1(2820.76,1460.93) 1(2820.76,1460.93) 1(2820.76,2135.93) 1(2820.76,2135.93) 1(2820.86,1707.71) 1(2820.86,1707.71) 1(2820.86,2382.71) 1(2820.86,2382.71) 1(2820.93,1461.22) 1(2820.93,1461.22) 1(2820.93,2136.22) 1(2820.93,2136.22) 1(2821.02,1707.41) 1(2821.02,1707.41) 1(2821.02,2382.41) 1(2821.02,2382.41) 1(2821.08,1461.53) 1(2821.08,1461.53) 1(2821.08,2136.53) 1(2821.08,2136.53) 1(2821.17,1707.1) 1(2821.17,1707.1) 1(2821.17,2382.1) 1(2821.17,2382.1) 1(2821.22,1461.85) 1(2821.22,1461.85) 1(2821.22,2136.85) 1(2821.22,2136.85) 1(2821.3,1706.77) 1(2821.3,1706.77) 1(2821.3,2381.77) 1(2821.3,2381.77) 1(2821.36,1462.18) 1(2821.36,1462.18) 1(2821.36,2137.18) 1(2821.36,2137.18) 1(2821.43,1706.43) 1(2821.43,1706.43) 1(2821.43,2381.43) 1(2821.43,2381.43) 1(2821.48,1462.52) 1(2821.48,1462.52) 1(2821.48,2137.52) 1(2821.48,2137.52) 1(2821.55,1706.09) 1(2821.55,1706.09) 1(2821.55,2381.09) 1(2821.55,2381.09) 1(2821.59,1462.87) 1(2821.59,1462.87) 1(2821.59,2137.87) 1(2821.59,2137.87) 1(2821.65,1705.73) 1(2821.65,1705.73) 1(2821.65,2380.73) 1(2821.65,2380.73) 1(2821.69,1463.23) 1(2821.69,1463.23) 1(2821.69,2138.23) 1(2821.69,2138.23) 1(2821.75,1705.37) 1(2821.75,1705.37) 1(2821.75,2380.37) 1(2821.75,2380.37) 1(2821.78,1463.59) 1(2821.78,1463.59) 1(2821.78,2138.59) 1(2821.78,2138.59) 1(2821.83,1705) 1(2821.83,1705) 1(2821.83,2380) 1(2821.83,2380) 1(2821.86,1463.97) 1(2821.86,1463.97) 1(2821.86,2138.97) 1(2821.86,2138.97) 1(2821.9,1704.62) 1(2821.9,1704.62) 1(2821.9,2379.62) 1(2821.9,2379.62) 1(2821.93,1464.35) 1(2821.93,1464.35) 1(2821.93,2139.35) 1(2821.93,2139.35) 1(2821.96,1704.24) 1(2821.96,1704.24) 1(2821.96,2379.24) 1(2821.96,2379.24) 1(2821.98,1464.73) 1(2821.98,1464.73) 1(2821.98,2139.73) 1(2821.98,2139.73) 1(2822.01,1703.85) 1(2822.01,1703.85) 1(2822.01,2378.85) 1(2822.01,2378.85) 1(2822.03,1465.12) 1(2822.03,1465.12) 1(2822.03,2140.12) 1(2822.03,2140.12) 1(2822.05,1703.46) 1(2822.05,1703.46) 1(2822.05,2378.46) 1(2822.05,2378.46) 1(2822.06,1465.51) 1(2822.06,1465.51) 1(2822.06,2140.51) 1(2822.06,2140.51) 1(2822.07,1703.07) 1(2822.07,1703.07) 1(2822.07,2378.07) 1(2822.07,2378.07) 1(2822.08,1465.9) 1(2822.08,1465.9) 1(2822.08,2140.9) 1(2822.08,2140.9) 1(2822.08,1427.8) 1(2822.08,1427.8) 1(2822.08,1466.29) 1(2822.08,1466.29) 1(2822.08,1702.51) 1(2822.08,1702.51) 1(2822.08,1741.01) 1(2822.08,1741.01) 1(2822.08,2102.8) 1(2822.08,2102.8) 1(2822.08,2141.29) 1(2822.08,2141.29) 1(2822.08,2377.51) 1(2822.08,2377.51) 1(2822.08,2416.01) 1(2822.08,2416.01)
  round 61.02 on Mech26: 1(835.02,-784.57) 1(835.02,-684.57) 1(901.39,-191.52) 1(901.39,-91.52) 1(1012.02,1024.43) 1(1012.02,1124.43) 1(1891.39,1893.48) 1(1891.39,1993.48) 1(2404.39,1178.48) 1(2404.39,1278.48)
  round 140 on Mech26: 1(850.04,3175.57)
  round 9.84 on Mech26: 1(1139.9,1303.94) 1(1149.74,1303.94) 1(1599.07,1036.83) 1(1607.57,1036.83) 1(1689.74,876.75) 1(1689.74,896.44) 1(1689.74,955.49) 1(1689.74,916.12) 1(1689.74,935.81) 1(1725.17,876.75) 1(1725.17,896.44) 1(1725.17,955.49) 1(1725.17,916.12) 1(1725.17,935.81) 1(1748.05,-259.47) 1(1748.05,-239.79) 1(1748.05,-180.73) 1(1748.05,-220.1) 1(1748.05,-200.42) 1(1783.48,-259.47) 1(1783.48,-239.79) 1(1783.48,-180.73) 1(1783.48,-220.1) 1(1783.48,-200.42) 1(1857.06,916.12) 1(1857.06,935.81) 1(1857.06,876.75) 1(1857.06,896.44) 1(1857.06,955.49) 1(1892.5,916.12) 1(1892.5,935.81) 1(1892.5,876.75) 1(1892.5,896.44) 1(1892.5,955.49) 1(1915.37,-220.1) 1(1915.37,-200.42) 1(1915.37,-259.47) 1(1915.37,-239.79) 1(1915.37,-180.73) 1(1950.8,-220.1) 1(1950.8,-200.42) 1(1950.8,-259.47) 1(1950.8,-239.79) 1(1950.8,-180.73) 1(2208.02,-42.89) 1(2208.02,-23.2) 1(2208.02,-3.52) 1(2208.02,16.17) 1(2208.02,35.85) 1(2243.45,-42.89) 1(2243.45,-23.2) 1(2243.45,-3.52) 1(2243.45,16.17) 1(2243.45,35.85) 1(2375.34,-42.89) 1(2375.34,-23.2) 1(2375.34,-3.52) 1(2375.34,16.17) 1(2375.34,35.85) 1(2410.77,-42.89) 1(2410.77,-23.2) 1(2410.77,-3.52) 1(2410.77,16.17) 1(2410.77,35.85) 1(2451.23,1570.71) 1(2484.74,2215.63)
  round 19.69 on Mech26: 1(1144.82,1303.94)
  round 27.56 on Mech26: 1(1183.2,1334.25)
  round 23.62 on Mech26: 1(1202.89,1365.75) 1(1226.51,1365.75) 1(1822.62,263.66)
  round 47.24 on Mech26: 1(1214.7,1365.75) 1(2707.23,1446.03) 1(2707.23,1721.62) 1(2707.23,2121.03) 1(2707.23,2396.62) 1(2734.79,1446.03) 1(2734.79,1721.62) 1(2734.79,2121.03) 1(2734.79,2396.62)
  round 125.2 on Mech26: 1(1248.4,-1445.57) 1(1748.4,-1445.57)
  round 8 on Mech26: 1(1404.02,868.14) 1(1404.02,898.48) 1(1559.75,624.68) 1(1559.75,624.68) 1(1567.19,564.82) 1(1567.19,632.13) 1(1567.19,632.13) 1(1568.83,632.13) 1(1576.27,624.68) 1(1576.27,624.68)
  round 6.89 on Mech26: 1(1623.45,1032.01) 1(1623.45,1038.9) 1(1623.45,1057.6) 1(1623.45,1064.49) 1(1623.45,1083.19) 1(1623.45,1090.08) 1(1623.45,1108.78) 1(1623.45,1115.67) 1(1683.49,1032.01) 1(1683.49,1038.9) 1(1683.49,1057.6) 1(1683.49,1064.49) 1(1683.49,1083.19) 1(1683.49,1090.08) 1(1683.49,1108.78) 1(1683.49,1115.67) 1(1847.86,1032.01) 1(1847.86,1038.9) 1(1847.86,1057.6) 1(1847.86,1064.49) 1(1847.86,1083.19) 1(1847.86,1090.08) 1(1847.86,1108.78) 1(1847.86,1115.67) 1(1907.9,1032.01) 1(1907.9,1038.9) 1(1907.9,1057.6) 1(1907.9,1064.49) 1(1907.9,1083.19) 1(1907.9,1090.08) 1(1907.9,1108.78) 1(1907.9,1115.67)
  round 6.69 on Mech26: 1(1689.43,18.08) 1(1689.43,41.7) 1(1695.66,626.08) 1(1695.66,649.7) 1(1783.92,18.08) 1(1783.92,41.7) 1(1790.15,626.08) 1(1790.15,649.7) 1(1795.35,-58.91) 1(1795.35,11.96) 1(1798.53,656.09) 1(1798.53,726.96) 1(1874.09,-58.91) 1(1874.09,11.96) 1(1877.28,656.09) 1(1877.28,726.96) 1(1887.35,-56.91) 1(1887.35,13.96) 1(1887.53,655.09) 1(1887.53,725.96) 1(1966.09,-56.91) 1(1966.09,13.96) 1(1966.28,655.09) 1(1966.28,725.96) 1(1978,626.08) 1(1978,649.7) 1(1979,18.08) 1(1979,41.7) 1(2072.49,626.08) 1(2072.49,649.7) 1(2073.49,18.08) 1(2073.49,41.7)
  round 2.76 on Mech26: 1(1693.37,-23.26) 1(1693.37,-23.26) 1(1693.37,83.04) 1(1693.37,83.04) 1(1699.6,584.74) 1(1699.6,584.74) 1(1699.6,691.04) 1(1699.6,691.04) 1(1779.98,-23.26) 1(1779.98,-23.26) 1(1779.98,83.04) 1(1779.98,83.04) 1(1786.21,584.74) 1(1786.21,584.74) 1(1786.21,691.04) 1(1786.21,691.04) 1(1797.32,-92.37) 1(1797.32,-92.37) 1(1797.32,45.42) 1(1797.32,45.42) 1(1800.5,622.63) 1(1800.5,622.63) 1(1800.5,760.42) 1(1800.5,760.42) 1(1872.13,-92.37) 1(1872.13,-92.37) 1(1872.13,45.42) 1(1872.13,45.42) 1(1875.31,622.63) 1(1875.31,622.63) 1(1875.31,760.42) 1(1875.31,760.42) 1(1889.32,-90.37) 1(1889.32,-90.37) 1(1889.32,47.42) 1(1889.32,47.42) 1(1889.5,621.63) 1(1889.5,621.63) 1(1889.5,759.42) 1(1889.5,759.42) 1(1964.13,-90.37) 1(1964.13,-90.37) 1(1964.13,47.42) 1(1964.13,47.42) 1(1964.31,621.63) 1(1964.31,621.63) 1(1964.31,759.42) 1(1964.31,759.42) 1(1981.94,584.74) 1(1981.94,584.74) 1(1981.94,691.04) 1(1981.94,691.04) 1(1982.94,-23.26) 1(1982.94,-23.26) 1(1982.94,83.04) 1(1982.94,83.04) 1(2068.55,584.74) 1(2068.55,584.74) 1(2068.55,691.04) 1(2068.55,691.04) 1(2069.55,-23.26) 1(2069.55,-23.26) 1(2069.55,83.04) 1(2069.55,83.04)
  round 21.42 on Mech26: 1(1803.22,1541.73)
  round 3.15 on Mech26: 1(1818.06,1422.25) 1(1818.06,1422.25) 1(1818.06,1524.61) 1(1818.06,1524.61) 1(1831.84,1504.92) 1(1847.59,1504.92) 1(1947.99,1422.25) 1(1947.99,1422.25) 1(1947.99,1524.61) 1(1947.99,1524.61)
  round 18.9 on Mech26: 1(1839.72,1504.92)
  round 74 on Mech26: 1(2229.53,465.36)
  round 26.34 on Mech26: 1(2259.77,880.15)
  round 80 on Mech26: 1(2277.39,-907.52)
  round 69.78 on Mech26: 1(2350.93,-316.04)
  round 22.01 on Mech26: 1(2443.86,1526.43)
  round 1.97 on Mech26: 1(2447.29,1570.71) 1(2455.17,1570.71) 1(2480.8,2215.63) 1(2488.68,2215.63)
  round 29.53 on Mech26: 1(2466,-1325.14) 1(2466,-1147.97) 1(2495.53,-1325.14) 1(2495.53,-1147.97)
  round 59.06 on Mech26: 1(2539.82,-1051.52) 1(2657.93,-1051.52) 1(2716.99,-1295.61) 1(2716.99,-1177.5)
  round 20.19 on Mech26: 1(2587.49,1635.88) 1(2587.49,2310.88)
  round 33.46 on Mech26: 1(2600.29,-805.1) 1(2600.29,-771.64) 1(2600.29,-360.1) 1(2600.29,-326.64) 1(2633.76,-805.1) 1(2633.76,-771.64) 1(2633.76,-360.1) 1(2633.76,-326.64)
  round 66.93 on Mech26: 1(2617.02,-650.57) 1(2617.02,-512.78) 1(2617.02,-205.57) 1(2617.02,-67.78)
  round 30.12 on Mech26: 1(2663.97,630.37) 1(2663.97,660.49) 1(2694.08,630.37) 1(2694.08,660.49)
  round 157.48 hole 118.11: TH1(132.04,3087.21) TH2(2371.69,132.18) TH4(2373.66,3084) TH9(131.63,132.18)
  round 160 hole 160 unplated: ""(150,3310.85) ""(150,-125.6) ""(2330.32,3310.85) ""(2330.32,-125.6)

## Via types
v1: diameter 18, hole 8, Top Layer to Bottom Layer, tented both sides, 2905 vias

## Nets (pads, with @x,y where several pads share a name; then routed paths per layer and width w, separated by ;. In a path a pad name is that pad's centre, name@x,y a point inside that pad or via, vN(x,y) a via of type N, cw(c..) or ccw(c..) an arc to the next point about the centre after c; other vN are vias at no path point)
3V3_LDO_EN: R11.2 R241.2 U13.8 | length 142
  Bottom Layer w6: R11.2@1584.56,753.71 1584.56,797.45 1600.37,813.26 U13.8@1676.26,813.26
5V_IN: C51.1 C56.1 C60.1 C62.1 C66.1 C67.1 C69.1 C72.1 C73.1 C74.1 C134.1 C135.1 J4.1 R9.1 R30.1 R31.1 R69.2 R76.2 R87.2 R141.1 R174.1 R232.1 R238.1 R244.1 U16.2 U16.7 U18.1 U18.2 U19.1 U19.2 U20.1 U20.2 | length 3395.4
  Top Layer w10: R141.1@1711.5,103.14 1731.98,103.14 v1(1748.59,86.52)
  Top Layer w12: 1694.17,1251.78 R174.1@1703.76,1251.78
  Top Layer w15: R69.2@260.75,1845.83 229.84,1845.83 220.47,1836.46 220.47,1738.05 243.74,1714.78 437.03,1714.78 537.49,1614.33 537.49,1529.32 456.57,1448.4 v1(261.78,1448.4) ; v1(1635.38,1261.02) 1684.94,1261.02 1694.17,1251.78
  Top Layer w20: R31.1@276.36,2714.2 271.1,2708.93 J4.1@67.09,2708.93 67.09,2402.45 100.91,2368.63 369.19,2368.63 398.51,2339.31 v1(398.51,2306.78)
  L5_PWR2 w30: v1(1748.59,86.52) 1891.26,229.18 2171.68,229.18 2288.99,346.48 2288.99,634.16 2098.85,824.3 1837.37,824.3
  other v1: 1594.04,911.56 1624.04,911.56 1605.38,1201.02 1635.38,1201.02 1605.38,1231.02 1635.38,1231.02 1605.38,1261.02 1605.38,1291.02 1635.38,1291.02 252.31,1463.58 234.16,1465.45 1532.05,2133.21 1555.24,2134.58 1532.05,2163.21 1555.24,2164.58 1532.05,2193.21 1555.24,2194.58 368.51,2276.78 398.51,2276.78 428.51,2276.78 458.51,2276.78 368.51,2306.78 428.51,2306.78 458.51,2306.78
5V_IN_USB: C46.2 C47.1 C50.1 C55.1 C84.1 C85.2 C137.1 D1.1 R1.2 U16.6
5V_REG: C49.1 C136.1 D2.1 R102.2 TP12.1 U16.3 U16.5
CAN_PHY_RX: R80.1 U12.5 | length 2265.7
  Top Layer w6: v1@259.06,1755.18 v1(259.36,1755.18) 277.49,1773.31 R80.1@277.49,1787.62
  Bottom Layer w6: v1@259.11,1755.18 191.02,1823.27 119,1823.27 86.66,1790.93 86.66,1394.5 120.03,1361.14 120.03,1164.96 142.21,1142.77 142.21,780.79 725.87,197.13 816.72,197.13 839.64,220.05 U12.5@869.18,220.05
CAN_PHY_TX: R78.1 U12.9 | length 2755
  Top Layer w6: R78.1@392.57,2030.57 470.84,2030.57 v1(477.25,2036.98)
  L3_SIG1 w6: v1(477.25,2036.98) 566.17,1948.06 566.17,1808.44 297.08,1539.35 297.08,577.13 388.36,485.85 948.97,485.85 976.17,458.65 976.17,332.72 1002.86,306.03 1002.86,286.56 1020.83,268.59 1035.74,268.59 1047.31,280.17 v1(1047.31,311.48)
  Bottom Layer w6: v1(1047.31,311.48) 1061.98,296.82 U12.9@1101.47,296.82
CAN_STB: R3.2 R71.2 U5.8 | length 132
  Top Layer w10: U5.8@551.08,1980.45 632.6,1980.45 R71.2@633.04,1980.88 633.04,1931.24 R3.2@633.21,1931.06
CAN_STB_CTRL: R3.1 S4.2 | length 1897
  Top Layer w8: R3.1@680.45,1931.06 719.24,1931.06 v1(730.29,1920.01) ; v1(2150.78,1523.83) 2167.14,1540.19 S4.2@2167.14,1592.74
  L6_SIG2 w6: v1(1311.68,1559.59) 1426.16,1559.59 v1(1479.42,1612.86)
  Bottom Layer w6: v1(730.29,1920.01) 768.89,1920.01 853.73,1835.17 853.73,1760.21 939.77,1674.17 1225.93,1674.17 1311.68,1588.42 v1(1311.68,1559.59) ; v1(1479.42,1612.86) 1522.55,1612.86 1544.22,1591.19 1613.31,1591.19 1632.82,1571.68 1856.71,1571.68 1921.16,1636.14 2062.43,1636.14 2109.83,1588.74 2109.83,1547.84 2133.84,1523.83 v1(2150.78,1523.83)
CANH: J3.3 R68.2 U5.7 | length 802
  Top Layer w6: J3.3@67.09,2114.66 68.6,2113.15 91.24,2113.15 132.71,2071.69 132.71,2022.11 172.6,1982.22 R68.2@224.88,1982.22 ; v1(481.35,1930.61) 550.92,1930.61 U5.7@551.08,1930.45
  L3_SIG1 w6: J3.3@67.09,2114.66 107.48,2114.66 291.53,1930.61 v1(481.35,1930.61)
CANL: J3.1 R79.1 U5.6 | length 775
  Top Layer w6: J3.1@67.09,2014.66 67.09,1974.66 107.09,1934.66 223.98,1934.66 R79.1@224.92,1935.61 ; v1(481.35,1880.61) U5.6@550.92,1880.61
  L3_SIG1 w6: J3.1@67.09,2014.66 102.28,2014.66 138.85,1978.09 138.85,1958.92 228.74,1869.03 469.77,1869.03 v1(481.35,1880.61)
CB_REG_1V2: C64.2 R183.1 R193.2 U8.9 | length 107.6
  Top Layer w9: U8.9@454.84,2193.45 500.63,2193.45 R193.2@544.36,2149.73
CB_REG_1V8: C1.2 R182.1 R192.2 U6.9 | length 105.8
  Bottom Layer w10: R192.2@1732.39,2159.94 1775.29,2117.04 U6.9@1775.29,2071.9
CB_REG_RF_1V2: C103.2 R92.1 R134.2 U25.9 | length 104.8
  Bottom Layer w10: U25.9@431.8,2909.57 431.8,2870.32 R134.2@478.14,2823.99
COMP1: R43.2 U18.4 | length 57.4
  Top Layer w10: U18.4@1877,1352.93 1877,1340.52 1883.43,1334.09 R43.2@1919.35,1334.09
COMP2: R178.2 U19.4 | length 57.3
  Bottom Layer w10: R178.2@225.59,2330.9 260.11,2330.9 266.47,2337.26 U19.4@266.47,2351.04
COMP3: R180.2 U20.4 | length 70.5
  Top Layer w6: R180.2@1591.34,1948.49 1578.59,1961.24 1578.59,1980.07 1588.26,1989.74 U20.4@1608.17,1989.74
CONN_5V: C92.1 C93.1 C96.2 J6.1 J6.2 J6.3 R30.2 | length 552.6
  Top Layer w20: v1(157.73,1463.71) 171.41,1450.03 171.41,1415.24 180.11,1406.54 R30.2@181.09,1406.54
  L5_PWR2 w40: v1(157.73,1463.71) 178.62,1442.82 178.62,1295.6 220.87,1253.35 v1(469.54,1253.35)
  other v1: 442,1252.39 145.86,1448.68
DCA_LP_HOST_INTR_1: J2.6 R23.2 R42.2 R133.2 R152.1 U24.12 | length 3047.3
  Top Layer w6: R42.2@616.93,1149.93 632.29,1149.93 639.75,1157.39 v1(639.75,1171.69)
  L6_SIG2 w6: v1(639.75,1171.69) 678.04,1133.4 678.04,1111.82 731.77,1058.1 772.71,1058.1 785.04,1070.42 785.04,1082.43 792.2,1089.59 v1(792.2,1104.84) ; v1(2030.04,1192.27) 2030.04,1173.16 2041.61,1161.59 2215.79,1161.59 2374.49,1320.3 J2.6@2420.41,1320.3
  Bottom Layer w6: v1(792.2,1104.84) 826.2,1104.84 844.75,1086.29 970.69,1086.29 1027.44,1029.54 1176.86,1029.54 1344.1,862.3 1488.11,862.3 1528.6,902.79 1528.6,1045.38 1562.59,1079.36 1651.39,1079.36 1733.62,997.13 1776.33,997.13 1833.26,940.2 1833.26,869.24 1856.94,845.55 1929.29,845.55 1971.21,887.47 1971.21,1095.42 1978.52,1102.73 R152.1@1978.52,1126.65 ; U24.12@1868.72,1108.61 1960.47,1108.61 R152.1@1978.52,1126.65 ; v1(2030.04,1192.27) 2011.9,1192.27 1981.32,1161.7 R23.2@1979.35,1161.7 1978.52,1160.86 R152.1@1978.52,1126.65 ; R133.2@2337.72,1469.82 2337.72,1436.58 v1(2346.27,1428.02) 2346.27,1345.13 2369.64,1321.77 2418.94,1321.77 J2.6@2420.41,1320.3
